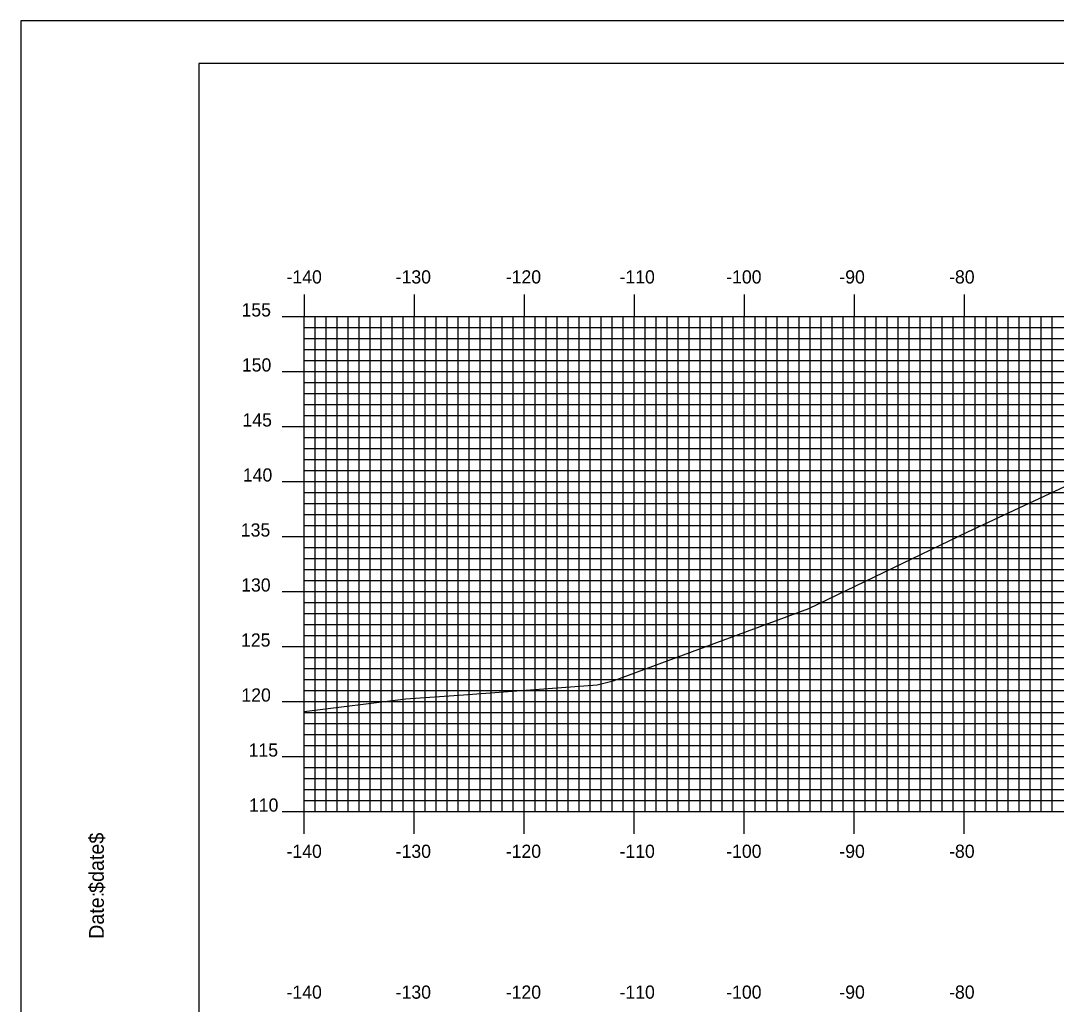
# Model space of a CAD drawing. Extents: x 860258 to 860601, y 364765 to 364985.
# Drawn here: x 860258.1 to 860352.3, y 364895.8 to 364985.2 of the extents above; entities that cross this region are included whole.
import ezdxf

# ---------------------------------------------------------------- set-up
doc = ezdxf.new("R2010")
doc.units = 0
for name, color, linetype in [('BORDER', 7, 'Continuous'), ('H_V ANNOTATION', 7, 'Continuous'), ('MAJOR', 7, 'Continuous'), ('MINOR', 7, 'Continuous'), ('PLOT BOUNDARY', 7, 'Continuous'), ('S_Roadway_Centerline', 7, 'Continuous')]:
    doc.layers.add(name, color=color, linetype=linetype)

msp = doc.modelspace()

# ---------------------------------------------------------------- linework, layer by layer
at = {"layer": 'BORDER'}
msp.add_lwpolyline([(860274.299, 364771.302), (860594.299, 364771.302), (860594.299, 364981.302), (860274.299, 364981.302)], close=True, dxfattribs=at)
at = {"layer": 'MAJOR'}
for p, q in [((860283.899, 364960.306), (860283.899, 364958.302)), ((860293.899, 364960.306), (860293.899, 364958.302)), ((860303.899, 364960.306), (860303.899, 364958.302)), ((860313.899, 364960.306), (860313.899, 364958.302)), ((860323.899, 364960.306), (860323.899, 364958.302)), ((860333.899, 364960.306), (860333.899, 364958.302)), ((860343.899, 364960.306), (860343.899, 364958.302)), ((860281.895, 364958.302), (860283.899, 364958.302)), ((860283.899, 364958.302), (860563.899, 364958.302)), ((860283.899, 364913.302), (860283.899, 364958.302)), ((860283.899, 364913.302), (860283.899, 364958.302)), ((860283.899, 364958.302), (860563.899, 364958.302)), ((860293.899, 364913.302), (860293.899, 364958.302)), ((860303.899, 364913.302), (860303.899, 364958.302)), ((860313.899, 364913.302), (860313.899, 364958.302)), ((860323.899, 364913.302), (860323.899, 364958.302)), ((860333.899, 364913.302), (860333.899, 364958.302)), ((860343.899, 364913.302), (860343.899, 364958.302)), ((860281.895, 364953.302), (860283.899, 364953.302)), ((860283.899, 364953.302), (860563.899, 364953.302)), ((860281.895, 364948.302), (860283.899, 364948.302)), ((860283.899, 364948.302), (860563.899, 364948.302)), ((860281.895, 364943.302), (860283.899, 364943.302)), ((860283.899, 364943.302), (860563.899, 364943.302)), ((860281.895, 364938.302), (860283.899, 364938.302)), ((860283.899, 364938.302), (860563.899, 364938.302)), ((860281.895, 364933.302), (860283.899, 364933.302)), ((860283.899, 364933.302), (860563.899, 364933.302)), ((860281.895, 364928.302), (860283.899, 364928.302)), ((860283.899, 364928.302), (860563.899, 364928.302)), ((860281.895, 364923.302), (860283.899, 364923.302)), ((860283.899, 364923.302), (860563.899, 364923.302)), ((860281.895, 364918.302), (860283.899, 364918.302)), ((860283.899, 364918.302), (860563.899, 364918.302)), ((860281.895, 364913.302), (860283.899, 364913.302)), ((860283.899, 364913.302), (860563.899, 364913.302)), ((860283.899, 364913.302), (860563.899, 364913.302)), ((860283.899, 364911.298), (860283.899, 364913.302)), ((860293.899, 364911.298), (860293.899, 364913.302)), ((860303.899, 364911.298), (860303.899, 364913.302)), ((860313.899, 364911.298), (860313.899, 364913.302)), ((860323.899, 364911.298), (860323.899, 364913.302)), ((860333.899, 364911.298), (860333.899, 364913.302)), ((860343.899, 364911.298), (860343.899, 364913.302))]:
    msp.add_line(p, q, dxfattribs=at)
at = {"layer": 'MINOR'}
for p, q in [((860284.899, 364913.302), (860284.899, 364958.302)), ((860285.899, 364913.302), (860285.899, 364958.302)), ((860286.899, 364913.302), (860286.899, 364958.302)), ((860287.899, 364913.302), (860287.899, 364958.302)), ((860288.899, 364913.302), (860288.899, 364958.302)), ((860289.899, 364913.302), (860289.899, 364958.302)), ((860290.899, 364913.302), (860290.899, 364958.302)), ((860291.899, 364913.302), (860291.899, 364958.302)), ((860292.899, 364913.302), (860292.899, 364958.302)), ((860294.899, 364913.302), (860294.899, 364958.302)), ((860295.899, 364913.302), (860295.899, 364958.302)), ((860296.899, 364913.302), (860296.899, 364958.302)), ((860297.899, 364913.302), (860297.899, 364958.302)), ((860298.899, 364913.302), (860298.899, 364958.302)), ((860299.899, 364913.302), (860299.899, 364958.302)), ((860300.899, 364913.302), (860300.899, 364958.302)), ((860301.899, 364913.302), (860301.899, 364958.302)), ((860302.899, 364913.302), (860302.899, 364958.302)), ((860304.899, 364913.302), (860304.899, 364958.302)), ((860305.899, 364913.302), (860305.899, 364958.302)), ((860306.899, 364913.302), (860306.899, 364958.302)), ((860307.899, 364913.302), (860307.899, 364958.302)), ((860308.899, 364913.302), (860308.899, 364958.302)), ((860309.899, 364913.302), (860309.899, 364958.302)), ((860310.899, 364913.302), (860310.899, 364958.302)), ((860311.899, 364913.302), (860311.899, 364958.302)), ((860312.899, 364913.302), (860312.899, 364958.302)), ((860314.899, 364913.302), (860314.899, 364958.302)), ((860315.899, 364913.302), (860315.899, 364958.302)), ((860316.899, 364913.302), (860316.899, 364958.302)), ((860317.899, 364913.302), (860317.899, 364958.302)), ((860318.899, 364913.302), (860318.899, 364958.302)), ((860319.899, 364913.302), (860319.899, 364958.302)), ((860320.899, 364913.302), (860320.899, 364958.302)), ((860321.899, 364913.302), (860321.899, 364958.302)), ((860322.899, 364913.302), (860322.899, 364958.302)), ((860324.899, 364913.302), (860324.899, 364958.302)), ((860325.899, 364913.302), (860325.899, 364958.302)), ((860326.899, 364913.302), (860326.899, 364958.302)), ((860327.899, 364913.302), (860327.899, 364958.302)), ((860328.899, 364913.302), (860328.899, 364958.302)), ((860329.899, 364913.302), (860329.899, 364958.302)), ((860330.899, 364913.302), (860330.899, 364958.302)), ((860331.899, 364913.302), (860331.899, 364958.302)), ((860332.899, 364913.302), (860332.899, 364958.302)), ((860334.899, 364913.302), (860334.899, 364958.302)), ((860335.899, 364913.302), (860335.899, 364958.302)), ((860336.899, 364913.302), (860336.899, 364958.302)), ((860337.899, 364913.302), (860337.899, 364958.302)), ((860338.899, 364913.302), (860338.899, 364958.302)), ((860339.899, 364913.302), (860339.899, 364958.302)), ((860340.899, 364913.302), (860340.899, 364958.302)), ((860341.899, 364913.302), (860341.899, 364958.302)), ((860342.899, 364913.302), (860342.899, 364958.302)), ((860344.899, 364913.302), (860344.899, 364958.302)), ((860345.899, 364913.302), (860345.899, 364958.302)), ((860346.899, 364913.302), (860346.899, 364958.302)), ((860347.899, 364913.302), (860347.899, 364958.302)), ((860348.899, 364913.302), (860348.899, 364958.302)), ((860349.899, 364913.302), (860349.899, 364958.302)), ((860350.899, 364913.302), (860350.899, 364958.302)), ((860351.899, 364913.302), (860351.899, 364958.302)), ((860283.899, 364957.302), (860563.899, 364957.302)), ((860283.899, 364957.302), (860285.903, 364957.302)), ((860283.899, 364956.302), (860563.899, 364956.302)), ((860283.899, 364956.302), (860285.903, 364956.302)), ((860283.899, 364955.302), (860563.899, 364955.302)), ((860283.899, 364955.302), (860285.903, 364955.302)), ((860283.899, 364954.302), (860563.899, 364954.302)), ((860283.899, 364954.302), (860285.903, 364954.302)), ((860283.899, 364952.302), (860563.899, 364952.302)), ((860283.899, 364952.302), (860285.903, 364952.302)), ((860283.899, 364951.302), (860563.899, 364951.302)), ((860283.899, 364951.302), (860285.903, 364951.302)), ((860283.899, 364950.302), (860563.899, 364950.302)), ((860283.899, 364950.302), (860285.903, 364950.302)), ((860283.899, 364949.302), (860563.899, 364949.302)), ((860283.899, 364949.302), (860285.903, 364949.302)), ((860283.899, 364947.302), (860563.899, 364947.302)), ((860283.899, 364947.302), (860285.903, 364947.302)), ((860283.899, 364946.302), (860563.899, 364946.302)), ((860283.899, 364946.302), (860285.903, 364946.302)), ((860283.899, 364945.302), (860563.899, 364945.302)), ((860283.899, 364945.302), (860285.903, 364945.302)), ((860283.899, 364944.302), (860563.899, 364944.302)), ((860283.899, 364944.302), (860285.903, 364944.302)), ((860283.899, 364942.302), (860563.899, 364942.302)), ((860283.899, 364942.302), (860285.903, 364942.302)), ((860283.899, 364941.302), (860563.899, 364941.302)), ((860283.899, 364941.302), (860285.903, 364941.302)), ((860283.899, 364940.302), (860563.899, 364940.302)), ((860283.899, 364940.302), (860285.903, 364940.302)), ((860283.899, 364939.302), (860563.899, 364939.302)), ((860283.899, 364939.302), (860285.903, 364939.302)), ((860283.899, 364937.302), (860563.899, 364937.302)), ((860283.899, 364937.302), (860285.903, 364937.302)), ((860283.899, 364936.302), (860563.899, 364936.302)), ((860283.899, 364936.302), (860285.903, 364936.302)), ((860283.899, 364935.302), (860563.899, 364935.302)), ((860283.899, 364935.302), (860285.903, 364935.302)), ((860283.899, 364934.302), (860563.899, 364934.302)), ((860283.899, 364934.302), (860285.903, 364934.302)), ((860283.899, 364932.302), (860563.899, 364932.302)), ((860283.899, 364932.302), (860285.903, 364932.302)), ((860283.899, 364931.302), (860563.899, 364931.302)), ((860283.899, 364931.302), (860285.903, 364931.302)), ((860283.899, 364930.302), (860563.899, 364930.302)), ((860283.899, 364930.302), (860285.903, 364930.302)), ((860283.899, 364929.302), (860563.899, 364929.302)), ((860283.899, 364929.302), (860285.903, 364929.302)), ((860283.899, 364927.302), (860563.899, 364927.302)), ((860283.899, 364927.302), (860285.903, 364927.302)), ((860283.899, 364926.302), (860563.899, 364926.302)), ((860283.899, 364926.302), (860285.903, 364926.302)), ((860283.899, 364925.302), (860563.899, 364925.302)), ((860283.899, 364925.302), (860285.903, 364925.302)), ((860283.899, 364924.302), (860563.899, 364924.302)), ((860283.899, 364924.302), (860285.903, 364924.302)), ((860283.899, 364922.302), (860563.899, 364922.302)), ((860283.899, 364922.302), (860285.903, 364922.302)), ((860283.899, 364921.302), (860563.899, 364921.302)), ((860283.899, 364921.302), (860285.903, 364921.302)), ((860283.899, 364920.302), (860563.899, 364920.302)), ((860283.899, 364920.302), (860285.903, 364920.302)), ((860283.899, 364919.302), (860563.899, 364919.302)), ((860283.899, 364919.302), (860285.903, 364919.302)), ((860283.899, 364917.302), (860563.899, 364917.302)), ((860283.899, 364917.302), (860285.903, 364917.302)), ((860283.899, 364916.302), (860563.899, 364916.302)), ((860283.899, 364916.302), (860285.903, 364916.302)), ((860283.899, 364915.302), (860563.899, 364915.302)), ((860283.899, 364915.302), (860285.903, 364915.302)), ((860283.899, 364914.302), (860563.899, 364914.302)), ((860283.899, 364914.302), (860285.903, 364914.302))]:
    msp.add_line(p, q, dxfattribs=at)
at = {"layer": 'PLOT BOUNDARY'}
msp.add_lwpolyline([(860258.113, 364765.184), (860598.113, 364765.184), (860598.113, 364985.184), (860258.113, 364985.184)], close=True, dxfattribs=at)
at = {"layer": 'S_Roadway_Centerline'}
msp.add_lwpolyline([(860283.899, 364922.406), (860293.145, 364923.544), (860298.387, 364923.905), (860310.52, 364924.829), (860311.969, 364925.194), (860329.764, 364931.774), (860344.239, 364938.746), (860360.971, 364946.563)], dxfattribs=at)

# ---------------------------------------------------------------- texts
at = {"layer": 'BORDER'}
for s, p in [('$date$', (860265.669, 364905.912)), ('Date:', (860265.669, 364901.736))]:
    msp.add_text(s, height=1.3392, rotation=90, dxfattribs=at).set_placement(p)
at = {"layer": 'H_V ANNOTATION'}
for s, p in [('-140', (860282.283, 364961.302)), ('-130', (860292.208, 364961.302)), ('-120', (860302.219, 364961.302)), ('-110', (860312.562, 364961.302)), ('-100', (860322.262, 364961.302)), ('-90', (860332.551, 364961.302)), ('-80', (860342.529, 364961.302)), ('155', (860278.191, 364958.302)), ('150', (860278.223, 364953.302)), ('145', (860278.277, 364948.302)), ('140', (860278.309, 364943.302)), ('135', (860278.127, 364938.302)), ('130', (860278.159, 364933.302)), ('125', (860278.148, 364928.302)), ('120', (860278.18, 364923.302)), ('115', (860278.834, 364918.302)), ('110', (860278.866, 364913.302)), ('-140', (860282.283, 364909.102)), ('-130', (860292.208, 364909.102)), ('-120', (860302.219, 364909.102)), ('-110', (860312.562, 364909.102)), ('-100', (860322.262, 364909.102)), ('-90', (860332.551, 364909.102)), ('-80', (860342.529, 364909.102)), ('-140', (860282.283, 364896.302)), ('-130', (860292.208, 364896.302)), ('-120', (860302.219, 364896.302)), ('-110', (860312.562, 364896.302)), ('-100', (860322.262, 364896.302)), ('-90', (860332.551, 364896.302)), ('-80', (860342.529, 364896.302))]:
    msp.add_text(s, height=1.2, dxfattribs=at).set_placement(p)
at = {"layer": 'MAJOR'}
msp.add_text('-', height=0.012, dxfattribs=at).set_placement((860283.89, 364913.302))

doc.saveas('drawing.dxf')
